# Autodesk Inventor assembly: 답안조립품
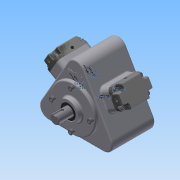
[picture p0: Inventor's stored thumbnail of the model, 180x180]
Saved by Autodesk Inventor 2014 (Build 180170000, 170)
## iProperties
Created: 2015-06
Part Number: 답안조립품
Document SubType Name: Assembly
Designer: MYHOME
Mass: 5318.58 g
Surface Area: 2414.93 cm^2
Volume: 1564.62 cm^3
Density: 3.39928 g/cm^3
Author: MYHOME
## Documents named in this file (20)
- C:\Documents and Settings\MYHOME\바탕 화면\350605V1035\답안조립품.iam
- C:\Documents and Settings\MYHOME\바탕 화면\350605V1035\본체.ipt
- C:\Documents and Settings\MYHOME\바탕 화면\350605V1035\베어링 NA 4904.ipt
- 베어링 NA 4904.ipt
- C:\Documents and Settings\MYHOME\바탕 화면\350605V1035\부시.ipt
- C:\Documents and Settings\MYHOME\바탕 화면\350605V1035\스프링1.ipt
- C:\Documents and Settings\MYHOME\바탕 화면\350605V1035\스프링2.ipt
- C:\Documents and Settings\MYHOME\바탕 화면\350605V1035\스프링3.ipt
- C:\Documents and Settings\MYHOME\바탕 화면\350605V1035\스프링4.ipt
- C:\Documents and Settings\MYHOME\바탕 화면\350605V1035\슬라이드.ipt
- C:\Documents and Settings\MYHOME\바탕 화면\350605V1035\앞커버.ipt
- C:\Documents and Settings\MYHOME\바탕 화면\350605V1035\오일실.ipt
- 오일실.ipt
- C:\Documents and Settings\MYHOME\바탕 화면\350605V1035\편심축.ipt
- C:\Documents and Settings\MYHOME\바탕 화면\350605V1035\헤더커버.ipt
- 헤더커버.ipt
- C:\Documents and Settings\MYHOME\바탕 화면\350605V1035\M6x0.7x20.ipt
- M6x0.7x20.ipt
- C:\Documents and Settings\MYHOME\바탕 화면\350605V1035\M4x0.5x16.ipt
- M4x0.5x16.ipt
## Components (14 placed, 3 different names)
1. 헤더커버:1
2. 헤더커버:2
3. M6x0.7x20:1
4. M6x0.7x20:2
5. M6x0.7x20:3
6. M6x0.7x20:4
7. M4x0.5x16:1
8. M4x0.5x16:2
9. M4x0.5x16:3
10. M4x0.5x16:4
11. M4x0.5x16:5
12. M4x0.5x16:6
13. M4x0.5x16:7
14. M4x0.5x16:8
